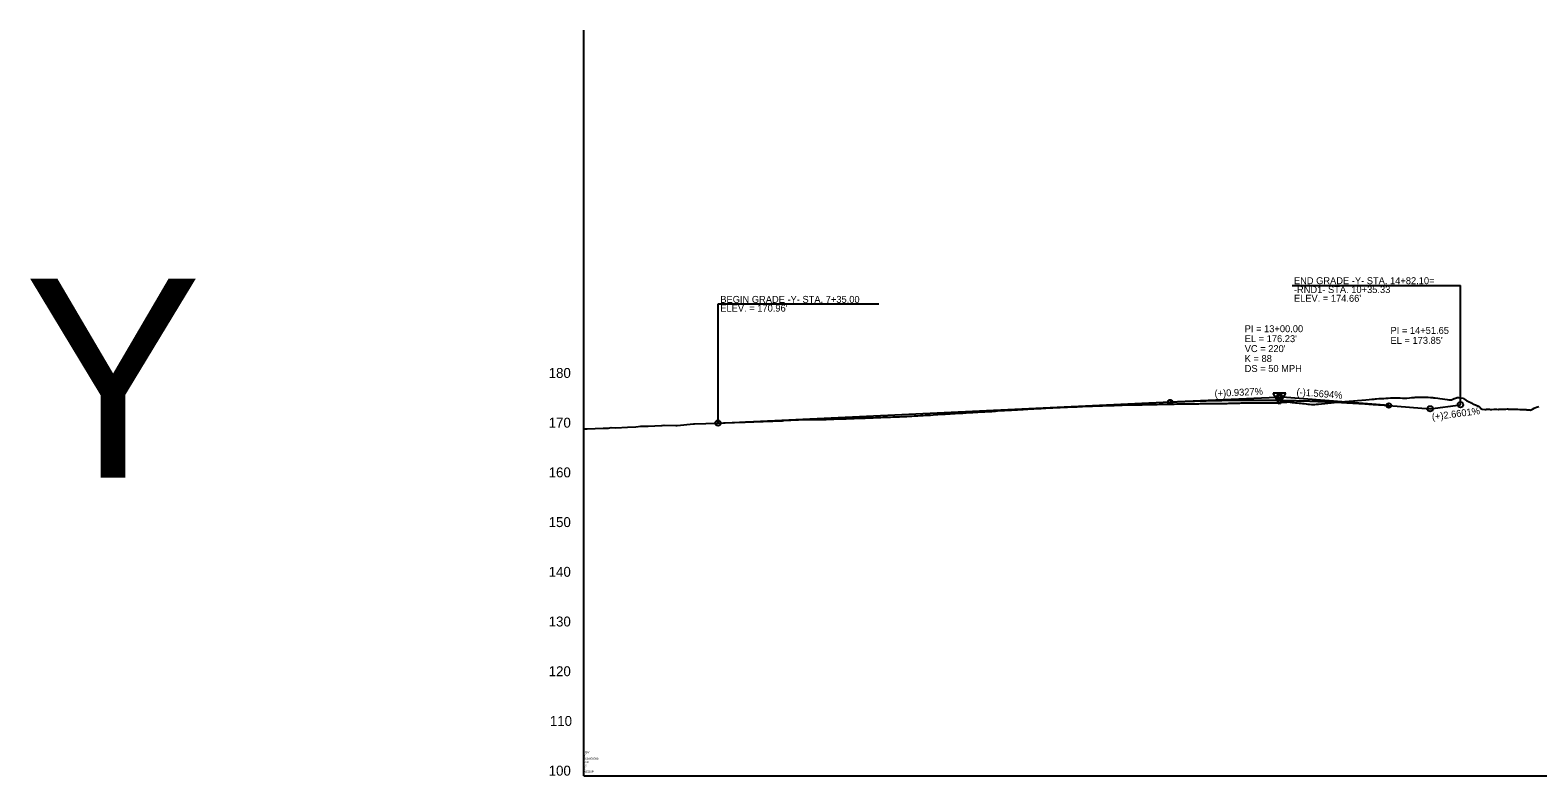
# Model space of a CAD drawing. Extents: x 1778432 to 1784301, y 601022 to 621789.
# Drawn here: x 1779586 to 1781103, y 620039 to 620789 of the extents above; entities that cross this region are included whole.
import ezdxf

# ---------------------------------------------------------------- set-up
doc = ezdxf.new("R2010")
doc.units = 0
for name, color, linetype in [('Exist Profile Cell', 7, 'Continuous'), ('Exist Vertical Profile Ground Line', 7, 'Continuous'), ('Exist Vertical Profile Vertical Axis Label', 7, 'Continuous'), ('Prop PFL Text', 7, 'Continuous'), ('Prop PFL VPI Symbol CELL', 7, 'Continuous'), ('Prop Vertical Profile Curve Label', 7, 'Continuous'), ('Prop Vertical Profile Grade', 7, 'Continuous'), ('Prop Vertical Profile Grade Label', 7, 'Continuous'), ('Prop VPI Label', 7, 'Continuous')]:
    doc.layers.add(name, color=color, linetype=linetype)

msp = doc.modelspace()

# ---------------------------------------------------------------- linework, layer by layer
at = {"layer": 'Exist Profile Cell'}
for q in [(1780143, 620789.2), (1783681.5, 620039.2), (1780143, 620039.2)]:
    msp.add_line((1780143, 620039.2), q, dxfattribs=at)
at = {"layer": 'Exist Vertical Profile Ground Line'}
msp.add_lwpolyline([(1780143, 620388.2), (1780146.3, 620388.1), (1780162.4, 620388.9), (1780167.8, 620389), (1780170.4, 620389.5), (1780175.3, 620389.2), (1780187, 620389.8), (1780195.2, 620390.2), (1780200.3, 620390.9), (1780207.6, 620390.8), (1780221.3, 620391.4), (1780221.7, 620391.4), (1780223.7, 620392), (1780235.4, 620391.5), (1780236.1, 620391.5), (1780237, 620391.5), (1780253.5, 620393.1), (1780254.5, 620393.1), (1780277.1, 620394), (1780278, 620394), (1780283.4, 620394.2), (1780284.4, 620394.3), (1780305, 620395), (1780305.9, 620395.1), (1780313.3, 620395.3), (1780314.2, 620395.4), (1780342.4, 620396.4), (1780343.2, 620396.5), (1780344.1, 620396.5), (1780358.4, 620397.1), (1780359.1, 620397.1), (1780381.7, 620397.6), (1780386.9, 620397.7), (1780389.3, 620397.8), (1780391.8, 620397.9), (1780394.4, 620398), (1780397, 620398.1), (1780399.3, 620398.1), (1780401.9, 620398.3), (1780404.5, 620398.3), (1780406.8, 620398.4), (1780409.4, 620398.5), (1780409.9, 620398.5), (1780412.2, 620398.6), (1780412.5, 620398.6), (1780415.1, 620398.7), (1780417.4, 620398.8), (1780419.3, 620398.9), (1780420, 620398.9), (1780422.3, 620399), (1780422.8, 620399), (1780424.9, 620399.1), (1780425.9, 620399.1), (1780426.6, 620399.2), (1780427.4, 620399.2), (1780428.7, 620399.2), (1780429.9, 620399.3), (1780430.6, 620399.3), (1780431.4, 620399.3), (1780432.2, 620399.4), (1780434, 620399.4), (1780436.6, 620399.5), (1780438.3, 620399.6), (1780438.9, 620399.6), (1780439.3, 620399.6), (1780441.5, 620399.7), (1780441.9, 620399.7), (1780443.9, 620399.8), (1780446, 620399.9), (1780446.6, 620399.9), (1780449.2, 620400), (1780451.5, 620400.1), (1780454, 620400.2), (1780455.4, 620400.2), (1780457.9, 620400.3), (1780460.5, 620400.4), (1780463, 620400.5), (1780465.4, 620400.6), (1780467.9, 620400.7), (1780470.5, 620400.9), (1780472.9, 620401), (1780475.4, 620401.2), (1780476.8, 620401.3), (1780479.1, 620401.4), (1780481.7, 620401.5), (1780484.3, 620401.7), (1780486.6, 620401.8), (1780489.2, 620402), (1780491.8, 620402.1), (1780494.4, 620402.3), (1780496.7, 620402.5), (1780499.3, 620402.7), (1780501.8, 620402.8), (1780504.1, 620402.9), (1780506.7, 620403.1), (1780509.3, 620403.3), (1780511.6, 620403.4), (1780513.8, 620403.6), (1780514.2, 620403.6), (1780516.8, 620403.7), (1780519, 620403.8), (1780519.4, 620403.9), (1780521.6, 620404), (1780524.2, 620404.1), (1780526.8, 620404.3), (1780527.8, 620404.3), (1780530.8, 620404.5), (1780532.4, 620404.5), (1780534, 620404.7), (1780534.4, 620404.7), (1780537.8, 620404.9), (1780539.5, 620405), (1780541.4, 620405.2), (1780544.7, 620405.4), (1780546.5, 620405.4), (1780548.6, 620405.6), (1780551.9, 620405.8), (1780553.6, 620405.8), (1780555.5, 620406.1), (1780557.2, 620406.1), (1780559.1, 620406.3), (1780562.7, 620406.5), (1780564.2, 620406.5), (1780565.8, 620406.7), (1780566.3, 620406.7), (1780569.1, 620406.9), (1780569.8, 620406.9), (1780571.3, 620406.9), (1780572.7, 620407.1), (1780573.1, 620407.1), (1780573.4, 620407.1), (1780576.2, 620407.3), (1780577, 620407.3), (1780578.5, 620407.4), (1780579.3, 620407.4), (1780579.6, 620407.5), (1780581.4, 620407.6), (1780581.9, 620407.6), (1780582.4, 620407.7), (1780584.5, 620407.7), (1780585.1, 620407.8), (1780587, 620407.9), (1780588.8, 620408), (1780589.4, 620408), (1780589.7, 620408), (1780591.6, 620408.2), (1780591.9, 620408.2), (1780592.7, 620408.2), (1780593.1, 620408.3), (1780595.3, 620408.4), (1780595.7, 620408.4), (1780597.8, 620408.5), (1780599.8, 620408.6), (1780600.5, 620408.7), (1780602.8, 620408.8), (1780603.2, 620408.8), (1780605.2, 620408.9), (1780607.3, 620409.1), (1780607.9, 620409.1), (1780610.5, 620409.2), (1780612.8, 620409.3), (1780614.9, 620409.4), (1780617.5, 620409.6), (1780620.1, 620409.7), (1780622.3, 620409.8), (1780624.9, 620409.9), (1780627.3, 620410), (1780627.6, 620410), (1780629.7, 620410.1), (1780631.8, 620410.2), (1780632.4, 620410.2), (1780634.6, 620410.3), (1780636.8, 620410.4), (1780639, 620410.5), (1780639.4, 620410.5), (1780642.1, 620410.7), (1780644.3, 620410.8), (1780644.7, 620410.8), (1780646.9, 620410.9), (1780649.5, 620411), (1780651.7, 620411), (1780652.7, 620411.1), (1780654.9, 620411.1), (1780656.3, 620411.2), (1780657.5, 620411.2), (1780659.8, 620411.3), (1780660.2, 620411.3), (1780662.4, 620411.4), (1780663.4, 620411.5), (1780665, 620411.5), (1780666.5, 620411.6), (1780666.8, 620411.6), (1780667.6, 620411.6), (1780669.8, 620411.7), (1780670.4, 620411.7), (1780671.5, 620411.7), (1780673.5, 620411.8), (1780674.1, 620411.8), (1780676.4, 620411.8), (1780677.3, 620411.9), (1780677.7, 620411.9), (1780679, 620411.9), (1780679.9, 620411.9), (1780681.2, 620412), (1780681.6, 620412), (1780683.8, 620412), (1780684.2, 620412.1), (1780685.5, 620412.2), (1780686.4, 620412.2), (1780687.2, 620412.2), (1780688.5, 620412.3), (1780689, 620412.3), (1780689.5, 620412.3), (1780690.1, 620412.3), (1780692.1, 620412.3), (1780694.4, 620412.4), (1780694.7, 620412.4), (1780696.3, 620412.4), (1780696.9, 620412.4), (1780697.3, 620412.5), (1780699.5, 620412.5), (1780700.1, 620412.5), (1780702, 620412.5), (1780703.9, 620412.5), (1780704.4, 620412.5), (1780704.8, 620412.5), (1780706.6, 620412.6), (1780707, 620412.6), (1780707.3, 620412.6), (1780707.6, 620412.6), (1780709.8, 620412.6), (1780712.4, 620412.7), (1780714.4, 620412.7), (1780715, 620412.8), (1780717.3, 620412.8), (1780717.7, 620412.8), (1780719.8, 620412.8), (1780721.9, 620412.9), (1780722.4, 620412.9), (1780725, 620412.9), (1780727.3, 620413), (1780729.9, 620413), (1780732.2, 620413.1), (1780734.6, 620413.1), (1780737.1, 620413.1), (1780739.6, 620413.2), (1780742.5, 620413.2), (1780744.5, 620413.3), (1780746, 620413.3), (1780747.1, 620413.3), (1780747.8, 620413.3), (1780749.8, 620413.3), (1780751.3, 620413.4), (1780752, 620413.4), (1780753.1, 620413.4), (1780753.7, 620413.4), (1780754.4, 620413.4), (1780754.9, 620413.4), (1780756.8, 620413.5), (1780757.2, 620413.5), (1780758.4, 620413.5), (1780759.1, 620413.5), (1780760.2, 620413.5), (1780761.9, 620413.5), (1780763.4, 620413.6), (1780763.7, 620413.6), (1780764.2, 620413.6), (1780765, 620413.6), (1780765.5, 620413.6), (1780766.2, 620413.6), (1780767.2, 620413.6), (1780768.4, 620413.6), (1780769, 620413.6), (1780769.3, 620413.6), (1780770, 620413.7), (1780770.8, 620413.7), (1780772.5, 620413.7), (1780773.1, 620413.7), (1780774.4, 620413.7), (1780776.5, 620413.8), (1780777.8, 620413.7), (1780778.6, 620413.7), (1780780.2, 620413.8), (1780781.6, 620413.8), (1780783.1, 620413.8), (1780784, 620413.8), (1780784.9, 620413.8), (1780786.3, 620413.8), (1780786.7, 620413.8), (1780787.9, 620413.8), (1780788.4, 620413.8), (1780789.6, 620413.8), (1780790.2, 620413.8), (1780792, 620413.9), (1780792.8, 620413.9), (1780793.8, 620413.9), (1780794.1, 620414), (1780795.5, 620414), (1780795.9, 620414), (1780797.3, 620414), (1780797.7, 620414), (1780799.1, 620414.1), (1780799.5, 620414.1), (1780799.9, 620414.1), (1780800.8, 620414.1), (1780801.3, 620414.1), (1780802.3, 620414.1), (1780802.6, 620414.1), (1780803, 620414.1), (1780804.4, 620414.2), (1780804.8, 620414.2), (1780805.4, 620414.2), (1780806.1, 620414.2), (1780806.6, 620414.2), (1780807.9, 620414.3), (1780808.5, 620414.3), (1780809.7, 620414.3), (1780810.2, 620414.3), (1780811.6, 620414.3), (1780812.6, 620414.3), (1780813.2, 620414.3), (1780813.8, 620414.3), (1780815, 620414.4), (1780816.9, 620414.4), (1780817.8, 620414.4), (1780818.5, 620414.4), (1780819.2, 620414.4), (1780820.3, 620414.4), (1780821.2, 620414.4), (1780822, 620414.4), (1780822.8, 620414.4), (1780823.8, 620414.4), (1780824.5, 620414.4), (1780825.6, 620414.4), (1780826.9, 620414.4), (1780827.3, 620414.4), (1780828.2, 620414.4), (1780829.1, 620414.4), (1780830.1, 620414.4), (1780830.9, 620414.4), (1780831.8, 620414.4), (1780832.8, 620414.4), (1780833.3, 620414.4), (1780834.7, 620414.4), (1780835.4, 620414.4), (1780835.8, 620414.4), (1780836.2, 620414.4), (1780837.3, 620414.5), (1780838, 620414.5), (1780839.7, 620414.4), (1780840.8, 620414.4), (1780841.5, 620414.5), (1780843.3, 620414.6), (1780845, 620414.7), (1780846.8, 620414.9), (1780847.5, 620414.9), (1780848.6, 620415), (1780849.3, 620415), (1780850.3, 620415.1), (1780851.7, 620415.2), (1780852.1, 620415.2), (1780853.9, 620415), (1780855.6, 620414.8), (1780857.4, 620414.7), (1780859.2, 620414.5), (1780860.9, 620414.3), (1780862.7, 620414.1), (1780864.5, 620414), (1780866.2, 620413.8), (1780868, 620413.6), (1780869.8, 620413.4), (1780871.6, 620413.1), (1780873.3, 620412.9), (1780875.1, 620412.7), (1780875.8, 620412.6), (1780876.9, 620412.7), (1780877.9, 620412.8), (1780878.6, 620412.8), (1780880.4, 620413), (1780882.2, 620413.1), (1780891.8, 620414), (1780901.3, 620415), (1780906.7, 620415.5), (1780908.8, 620415.6), (1780913, 620416.1), (1780929.8, 620417.5), (1780933.4, 620417.8), (1780935.8, 620418), (1780938.2, 620418.2), (1780939.6, 620418.4), (1780940.6, 620418.5), (1780942.9, 620418.6), (1780945.3, 620418.7), (1780947.7, 620418.8), (1780948.1, 620418.8), (1780950, 620419), (1780952.4, 620419.1), (1780954.8, 620419.3), (1780957.1, 620419.5), (1780959.5, 620419.5), (1780961.6, 620419.4), (1780961.9, 620419.4), (1780964.3, 620419.3), (1780966.9, 620419.1), (1780969, 620419.1), (1780971.3, 620419.1), (1780973.7, 620419.3), (1780976.1, 620419.6), (1780978.5, 620419.8), (1780979.6, 620419.9), (1780980.8, 620420), (1780983.2, 620420.1), (1780985.6, 620420.2), (1780986.7, 620420.2), (1780988, 620420.2), (1780990.3, 620420.2), (1780991.1, 620420.1), (1780992.7, 620420), (1780995.1, 620419.8), (1780997.4, 620419.6), (1780998.4, 620419.5), (1780999.8, 620419.3), (1781002.2, 620419), (1781004.5, 620418.7), (1781006.9, 620418.4), (1781009.3, 620418.1), (1781011.7, 620417.7), (1781013.4, 620417.5), (1781014.2, 620417.5), (1781016.1, 620417.3), (1781018.8, 620418.6), (1781019.2, 620418.8), (1781021.1, 620419.5), (1781021.9, 620419.8), (1781023.6, 620419.6), (1781025.9, 620419.3), (1781027.9, 620418.9), (1781028.2, 620418.7), (1781030.6, 620417.2), (1781031.6, 620416.5), (1781033.3, 620415.6), (1781033.9, 620415.4), (1781035.4, 620414.7), (1781035.8, 620414.5), (1781036.8, 620413.9), (1781037.7, 620413.3), (1781038.2, 620413), (1781040.1, 620412.2), (1781042.1, 620411.4), (1781042.5, 620411.2), (1781043.8, 620410.6), (1781044.8, 620409.6), (1781045.6, 620408.8), (1781047, 620407.9), (1781049.6, 620407.8), (1781050.9, 620407.7), (1781051.3, 620407.9), (1781051.9, 620407.9), (1781053.2, 620407.9), (1781054.3, 620407.9), (1781055.2, 620407.8), (1781056.8, 620407.7), (1781059.1, 620408), (1781059.5, 620408), (1781059.9, 620408.1), (1781061.5, 620407.9), (1781063, 620407.8), (1781063.8, 620407.9), (1781066.2, 620408.1), (1781066.8, 620408.1), (1781067.9, 620408), (1781068.6, 620408), (1781069.2, 620407.9), (1781070.9, 620408.1), (1781072.3, 620408.2), (1781072.7, 620408.2), (1781073.3, 620408.1), (1781075.6, 620408), (1781076.3, 620408), (1781078, 620408.1), (1781078.5, 620408.1), (1781079.5, 620408.1), (1781080.4, 620408), (1781081.1, 620407.9), (1781081.6, 620407.9), (1781082.9, 620407.9), (1781084.8, 620407.8), (1781085.1, 620407.8), (1781086, 620407.8), (1781087.5, 620407.7), (1781088.2, 620407.6), (1781088.5, 620407.6), (1781090, 620407.5), (1781091.2, 620407.5), (1781091.8, 620407.4), (1781092.2, 620407.4), (1781093.1, 620407.4), (1781093.4, 620407.4), (1781094.8, 620407.3), (1781095.6, 620407.1), (1781097, 620407.8), (1781097.7, 620408.1), (1781099.3, 620408.9), (1781099.9, 620409.2), (1781101.7, 620409.9), (1781104.1, 620410.7)], dxfattribs=at)
at = {"layer": 'Prop PFL VPI Symbol CELL'}
for p, q in [((1780843, 620412.9), (1780836.5, 620424.1)), ((1780849.4, 620424.1), (1780836.5, 620424.1)), ((1780843, 620412.9), (1780849.4, 620424.1))]:
    msp.add_line(p, q, dxfattribs=at)
for radius in [1.75, 1.2]:
    msp.add_circle((1780843, 620420.4), radius, dxfattribs=at)
at = {"layer": 'Prop Vertical Profile Curve Label'}
for centre in [(1780733, 620415.2), (1780953, 620411.7)]:
    msp.add_circle(centre, 2.25, dxfattribs=at)
at = {"layer": 'Prop Vertical Profile Grade'}
for p, q in [((1780278, 620394), (1780733, 620415.2)), ((1780953, 620411.7), (1780994.6, 620408.4)), ((1780994.6, 620408.4), (1781025.1, 620412.5))]:
    msp.add_line(p, q, dxfattribs=at)
msp.add_spline([(1780733, 620415.2), (1780737.4, 620415.4), (1780741.8, 620415.6), (1780746.2, 620415.8), (1780750.6, 620416), (1780755, 620416.1), (1780759.4, 620416.3), (1780763.8, 620416.4), (1780768.2, 620416.5), (1780772.6, 620416.6), (1780777, 620416.7), (1780781.4, 620416.8), (1780785.8, 620416.9), (1780790.2, 620417), (1780794.6, 620417), (1780799, 620417.1), (1780803.4, 620417.1), (1780807.8, 620417.1), (1780812.2, 620417.1), (1780816.6, 620417.1), (1780821, 620417.1), (1780825.4, 620417.1), (1780829.8, 620417.1), (1780834.2, 620417), (1780838.6, 620417), (1780843, 620416.9), (1780847.4, 620416.8), (1780851.8, 620416.8), (1780856.2, 620416.7), (1780860.6, 620416.5), (1780865, 620416.4), (1780869.4, 620416.3), (1780873.8, 620416.2), (1780878.2, 620416), (1780882.6, 620415.8), (1780887, 620415.7), (1780891.4, 620415.5), (1780895.8, 620415.3), (1780900.2, 620415.1), (1780904.6, 620414.9), (1780909, 620414.6), (1780913.4, 620414.4), (1780917.8, 620414.1), (1780922.2, 620413.9), (1780926.6, 620413.6), (1780931, 620413.3), (1780935.4, 620413), (1780939.8, 620412.7), (1780944.2, 620412.4), (1780948.6, 620412.1), (1780953, 620411.7)], degree=3, dxfattribs=at)
at = {"layer": 'Prop VPI Label'}
for p, q in [((1780855.9, 620532.5), (1781025.1, 620532.5)), ((1781025.1, 620412.5), (1781025.1, 620532.5)), ((1780278, 620394), (1780278, 620514)), ((1780278, 620514), (1780439.9, 620514)), ((1780733, 620415.2), (1780840.2, 620420.2)), ((1780953, 620411.7), (1780845.7, 620420.1))]:
    msp.add_line(p, q, dxfattribs=at)
for centre in [(1780843, 620420.4), (1780994.6, 620408.4), (1781025.1, 620412.5), (1780278, 620394)]:
    msp.add_circle(centre, 2.75, dxfattribs=at)

# ---------------------------------------------------------------- texts
at = {"layer": 'Exist Profile Cell'}
for s, p in [('Y', (1780143, 620058.7)), ('600.000000', (1780143, 620055.4)), ('RDY', (1780143, 620061.9)), ('100', (1780143, 620052.2)), ('2', (1780143, 620045.7)), ('10', (1780143, 620048.9)), ('NOGAP', (1780143, 620042.4))]:
    msp.add_text(s, height=2, dxfattribs=at).set_placement(p)
at = {"layer": 'Exist Vertical Profile Vertical Axis Label'}
for s, p in [('180', (1780107.6, 620439.4)), ('170', (1780107.6, 620389.4)), ('160', (1780107.6, 620339.4)), ('150', (1780107.6, 620289.4)), ('140', (1780107.6, 620239.4)), ('130', (1780107.6, 620189.4)), ('120', (1780107.6, 620139.4)), ('110', (1780108.8, 620089.4)), ('100', (1780107.6, 620039.4))]:
    msp.add_text(s, height=10, dxfattribs=at).set_placement(p)
at = {"layer": 'Prop PFL Text'}
msp.add_text('Y', height=200, dxfattribs=at).set_placement((1779580, 620339.2))
at = {"layer": 'Prop Vertical Profile Curve Label'}
for s, p in [("VC = 220'", (1780808, 620465.4)), ('K = 88', (1780808, 620455.4)), ('DS = 50 MPH', (1780808, 620445.4))]:
    msp.add_text(s, height=7, dxfattribs=at).set_placement(p)
at = {"layer": 'Prop Vertical Profile Grade Label'}
for s, rotation, p in [('(+)0.9327%', 2.6739, (1780777.8, 620420.3)), ('(-)1.5694%', 355.5059, (1780859.9, 620422)), ('(+)2.6601%', 7.5336, (1780996.8, 620396.7))]:
    msp.add_text(s, height=7, rotation=rotation, dxfattribs=at).set_placement(p)
at = {"layer": 'Prop VPI Label'}
for s, p in [('END GRADE -Y- STA. 14+82.10=', (1780857.5, 620533.7)), ('BEGIN GRADE -Y- STA. 7+35.00', (1780280.3, 620514.9)), ('-RND1- STA. 10+35.33', (1780857.5, 620524.8)), ("ELEV. = 174.66'", (1780857.5, 620516)), ("ELEV. = 170.96'", (1780280.3, 620506.1)), ('PI = 13+00.00', (1780808, 620485.4)), ("EL = 176.23'", (1780808, 620475.4)), ('PI = 14+51.65', (1780954.7, 620483.7)), ("EL = 173.85'", (1780954.7, 620473.7))]:
    msp.add_text(s, height=7, dxfattribs=at).set_placement(p)

doc.saveas('drawing.dxf')
